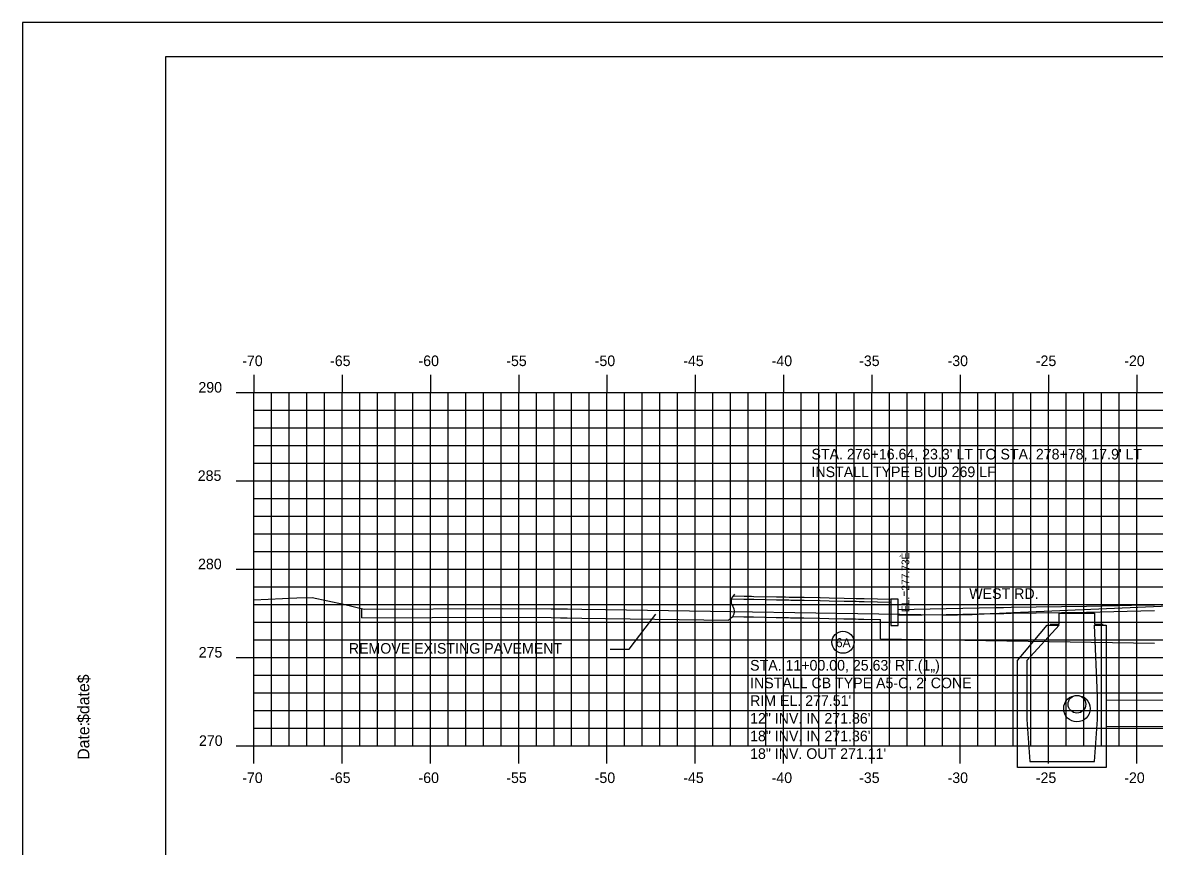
# Model space of a CAD drawing. Extents: x 853785 to 853955, y 366268 to 366378.
# Drawn here: x 853785.3 to 853849.4, y 366331.6 to 366378.2 of the extents above; entities that cross this region are included whole.
import ezdxf

# ---------------------------------------------------------------- set-up
doc = ezdxf.new("R2010")
doc.units = 0
for name, color, linetype in [('ANNOTATION', 7, 'Continuous'), ('BORDER', 7, 'Continuous'), ('D_Curb_Type1_Lt', 7, 'Continuous'), ('D_Drainage_CB_Shape5_Lt', 7, 'Continuous'), ('D_Drainage_Culvert', 7, 'Continuous'), ('D_Drainage_Text', 7, 'Continuous'), ('D_Roadway_Edge_Shoulder', 7, 'Continuous'), ('D_Roadway_Sidewalks_Paved', 7, 'Continuous'), ('D_Roadway_SubGrade', 7, 'Continuous'), ('D_Text_Standard', 7, 'Continuous'), ('H_V ANNOTATION', 7, 'Continuous'), ('MAJOR', 7, 'Continuous'), ('MINOR', 7, 'Continuous'), ('PDRAIN', 7, 'Continuous'), ('PLOT BOUNDARY', 7, 'Continuous'), ('S_Roadway_Centerline', 7, 'Continuous')]:
    doc.layers.add(name, color=color, linetype=linetype)

msp = doc.modelspace()

# ---------------------------------------------------------------- linework, layer by layer
at = {"layer": 'ANNOTATION'}
msp.add_lwpolyline([(853818.622, 366342.714), (853819.69, 366342.714), (853821.197, 366344.692)], dxfattribs=at)
at = {"layer": 'BORDER'}
for p, q in [((853953.435, 366376.236), (853793.435, 366376.236)), ((853793.435, 366376.236), (853793.435, 366271.236))]:
    msp.add_line(p, q, dxfattribs=at)
at = {"layer": 'D_Curb_Type1_Lt'}
msp.add_lwpolyline([(853834.514, 366345.548), (853834.514, 366344.048), (853834.931, 366344.048), (853834.931, 366345.548)], close=True, dxfattribs=at)
at = {"layer": 'D_Drainage_CB_Shape5_Lt'}
msp.add_lwpolyline([(853843.527, 366344.123), (853844.052, 366344.123), (853844.052, 366344.746), (853846.053, 366344.746), (853846.053, 366344.123), (853846.545, 366344.123)], dxfattribs=at)
msp.add_lwpolyline([(853846.709, 366344.081), (853846.709, 366336.018), (853841.689, 366336.018), (853841.689, 366342.081), (853843.363, 366344.081), (853844.052, 366344.081), (853842.214, 366342.081), (853842.214, 366340.079), (853842.214, 366338.734), (853842.378, 366336.346), (853846.053, 366336.346), (853846.217, 366338.734), (853846.217, 366340.079), (853846.053, 366344.081)], close=True, dxfattribs=at)
at = {"layer": 'D_Drainage_Culvert'}
for p, q in [((853846.709, 366339.851), (853883.967, 366339.636)), ((853846.709, 366338.351), (853883.958, 366338.136))]:
    msp.add_line(p, q, dxfattribs=at)
msp.add_circle((853845.052, 366339.346), 0.75, dxfattribs=at)
at = {"layer": 'D_Drainage_Text'}
msp.add_circle((853831.801, 366343.107), 0.625, dxfattribs=at)
at = {"layer": 'D_Roadway_Edge_Shoulder'}
for points in [[(853834.931, 366344.965), (853837.645, 366345.011), (853840.458, 366345.065), (853840.894, 366345.073), (853841.32, 366345.082), (853845.594, 366345.148), (853847.367, 366345.186), (853848.927, 366345.219), (853849.435, 366345.228)], [(853834.931, 366344.632), (853837.651, 366344.678), (853840.465, 366344.732), (853840.901, 366344.74), (853841.326, 366344.749), (853845.6, 366344.815), (853849.435, 366344.896)]]:
    msp.add_lwpolyline(points, dxfattribs=at)
at = {"layer": 'D_Roadway_Sidewalks_Paved'}
for points in [[(853825.482, 366345.559), (853826.195, 366345.546), (853826.246, 366345.545), (853826.275, 366345.544), (853826.621, 366345.538), (853826.74, 366345.536), (853826.758, 366345.536), (853828.04, 366345.511), (853828.543, 366345.502), (853828.742, 366345.498), (853828.852, 366345.496), (853829.597, 366345.481), (853830.507, 366345.463), (853831.016, 366345.453), (853831.868, 366345.436), (853832.538, 366345.423), (853832.708, 366345.419), (853832.998, 366345.413), (853834.511, 366345.382)], [(853825.566, 366345.724), (853826.198, 366345.713), (853826.249, 366345.712), (853826.278, 366345.711), (853826.624, 366345.705), (853826.744, 366345.702), (853826.761, 366345.702), (853828.043, 366345.677), (853828.546, 366345.668), (853828.745, 366345.664), (853828.855, 366345.662), (853829.6, 366345.648), (853830.51, 366345.63), (853831.02, 366345.619), (853831.871, 366345.603), (853832.541, 366345.589), (853832.712, 366345.586), (853833.001, 366345.58), (853834.514, 366345.549)]]:
    msp.add_lwpolyline(points, dxfattribs=at)
at = {"layer": 'D_Roadway_SubGrade'}
for p, q in [((853804.549, 366344.479), (853804.549, 366344.979)), ((853825.489, 366344.501), (853825.312, 366344.35)), ((853833.931, 366343.3), (853833.931, 366344.392)), ((853833.931, 366343.3), (853849.435, 366343.056))]:
    msp.add_line(p, q, dxfattribs=at)
for points in [[(853804.549, 366344.479), (853812.519, 366344.519), (853815.27, 366344.497), (853815.804, 366344.491), (853816.186, 366344.487), (853817.006, 366344.476), (853818.343, 366344.458), (853825.312, 366344.35)], [(853825.545, 366344.558), (853826.177, 366344.546), (853826.229, 366344.545), (853826.257, 366344.545), (853826.602, 366344.538), (853826.722, 366344.536), (853826.74, 366344.536), (853828.021, 366344.511), (853828.524, 366344.502), (853828.723, 366344.498), (853828.833, 366344.496), (853829.578, 366344.482), (853830.486, 366344.464), (853830.996, 366344.453), (853831.848, 366344.436), (853832.517, 366344.423), (853832.687, 366344.419), (853832.977, 366344.413), (853833.931, 366344.394)]]:
    msp.add_lwpolyline(points, dxfattribs=at)
for centre, radius, start, end in [((853825.95, 366345.425), 0.486, 125.81593, 215.81593), ((853825.207, 366344.854), 0.452, 308.64564, 39.40492)]:
    msp.add_arc(centre, radius, start, end, dxfattribs=at)
at = {"layer": 'MAJOR'}
for p, q in [((853798.435, 366358.238), (853798.435, 366357.236)), ((853803.435, 366358.238), (853803.435, 366357.236)), ((853808.435, 366358.238), (853808.435, 366357.236)), ((853813.435, 366358.238), (853813.435, 366357.236)), ((853818.435, 366358.238), (853818.435, 366357.236)), ((853823.435, 366358.238), (853823.435, 366357.236)), ((853828.435, 366358.238), (853828.435, 366357.236)), ((853833.435, 366358.238), (853833.435, 366357.236)), ((853838.435, 366358.238), (853838.435, 366357.236)), ((853843.435, 366358.238), (853843.435, 366357.236)), ((853848.435, 366358.238), (853848.435, 366357.236)), ((853797.433, 366357.236), (853798.435, 366357.236)), ((853798.435, 366357.236), (853938.435, 366357.236)), ((853798.435, 366337.236), (853798.435, 366357.236)), ((853798.435, 366337.236), (853798.435, 366357.236)), ((853798.435, 366357.236), (853938.435, 366357.236)), ((853803.435, 366337.236), (853803.435, 366357.236)), ((853808.435, 366337.236), (853808.435, 366357.236)), ((853813.435, 366337.236), (853813.435, 366357.236)), ((853818.435, 366337.236), (853818.435, 366357.236)), ((853823.435, 366337.236), (853823.435, 366357.236)), ((853828.435, 366337.236), (853828.435, 366357.236)), ((853833.435, 366337.236), (853833.435, 366357.236)), ((853838.435, 366337.236), (853838.435, 366357.236)), ((853843.435, 366337.236), (853843.435, 366357.236)), ((853848.435, 366337.236), (853848.435, 366357.236)), ((853797.433, 366352.236), (853798.435, 366352.236)), ((853798.435, 366352.236), (853938.435, 366352.236)), ((853797.433, 366347.236), (853798.435, 366347.236)), ((853798.435, 366347.236), (853938.435, 366347.236)), ((853797.433, 366342.236), (853798.435, 366342.236)), ((853798.435, 366342.236), (853938.435, 366342.236)), ((853797.433, 366337.236), (853798.435, 366337.236)), ((853798.435, 366337.236), (853938.435, 366337.236)), ((853798.435, 366337.236), (853938.435, 366337.236)), ((853798.435, 366336.234), (853798.435, 366337.236)), ((853803.435, 366336.234), (853803.435, 366337.236)), ((853808.435, 366336.234), (853808.435, 366337.236)), ((853813.435, 366336.234), (853813.435, 366337.236)), ((853818.435, 366336.234), (853818.435, 366337.236)), ((853823.435, 366336.234), (853823.435, 366337.236)), ((853828.435, 366336.234), (853828.435, 366337.236)), ((853833.435, 366336.234), (853833.435, 366337.236)), ((853838.435, 366336.234), (853838.435, 366337.236)), ((853843.435, 366336.234), (853843.435, 366337.236)), ((853848.435, 366336.234), (853848.435, 366337.236))]:
    msp.add_line(p, q, dxfattribs=at)
at = {"layer": 'MINOR'}
for p, q in [((853799.435, 366337.236), (853799.435, 366357.236)), ((853800.435, 366337.236), (853800.435, 366357.236)), ((853801.435, 366337.236), (853801.435, 366357.236)), ((853802.435, 366337.236), (853802.435, 366357.236)), ((853804.435, 366337.236), (853804.435, 366357.236)), ((853805.435, 366337.236), (853805.435, 366357.236)), ((853806.435, 366337.236), (853806.435, 366357.236)), ((853807.435, 366337.236), (853807.435, 366357.236)), ((853809.435, 366337.236), (853809.435, 366357.236)), ((853810.435, 366337.236), (853810.435, 366357.236)), ((853811.435, 366337.236), (853811.435, 366357.236)), ((853812.435, 366337.236), (853812.435, 366357.236)), ((853814.435, 366337.236), (853814.435, 366357.236)), ((853815.435, 366337.236), (853815.435, 366357.236)), ((853816.435, 366337.236), (853816.435, 366357.236)), ((853817.435, 366337.236), (853817.435, 366357.236)), ((853819.435, 366337.236), (853819.435, 366357.236)), ((853820.435, 366337.236), (853820.435, 366357.236)), ((853821.435, 366337.236), (853821.435, 366357.236)), ((853822.435, 366337.236), (853822.435, 366357.236)), ((853824.435, 366337.236), (853824.435, 366357.236)), ((853825.435, 366337.236), (853825.435, 366357.236)), ((853826.435, 366337.236), (853826.435, 366357.236)), ((853827.435, 366337.236), (853827.435, 366357.236)), ((853829.435, 366337.236), (853829.435, 366357.236)), ((853830.435, 366337.236), (853830.435, 366357.236)), ((853831.435, 366337.236), (853831.435, 366357.236)), ((853832.435, 366337.236), (853832.435, 366357.236)), ((853834.435, 366337.236), (853834.435, 366357.236)), ((853835.435, 366337.236), (853835.435, 366357.236)), ((853836.435, 366337.236), (853836.435, 366357.236)), ((853837.435, 366337.236), (853837.435, 366357.236)), ((853839.435, 366337.236), (853839.435, 366357.236)), ((853840.435, 366337.236), (853840.435, 366357.236)), ((853841.435, 366337.236), (853841.435, 366357.236)), ((853842.435, 366337.236), (853842.435, 366357.236)), ((853844.435, 366337.236), (853844.435, 366357.236)), ((853845.435, 366337.236), (853845.435, 366357.236)), ((853846.435, 366337.236), (853846.435, 366357.236)), ((853847.435, 366337.236), (853847.435, 366357.236)), ((853798.435, 366356.236), (853938.435, 366356.236)), ((853798.435, 366356.236), (853799.437, 366356.236)), ((853798.435, 366355.236), (853938.435, 366355.236)), ((853798.435, 366355.236), (853799.437, 366355.236)), ((853798.435, 366354.236), (853938.435, 366354.236)), ((853798.435, 366354.236), (853799.437, 366354.236)), ((853798.435, 366353.236), (853938.435, 366353.236)), ((853798.435, 366353.236), (853799.437, 366353.236)), ((853798.435, 366351.236), (853938.435, 366351.236)), ((853798.435, 366351.236), (853799.437, 366351.236)), ((853798.435, 366350.236), (853938.435, 366350.236)), ((853798.435, 366350.236), (853799.437, 366350.236)), ((853798.435, 366349.236), (853938.435, 366349.236)), ((853798.435, 366349.236), (853799.437, 366349.236)), ((853798.435, 366348.236), (853938.435, 366348.236)), ((853798.435, 366348.236), (853799.437, 366348.236)), ((853798.435, 366346.236), (853938.435, 366346.236)), ((853798.435, 366346.236), (853799.437, 366346.236)), ((853798.435, 366345.236), (853938.435, 366345.236)), ((853798.435, 366345.236), (853799.437, 366345.236)), ((853798.435, 366344.236), (853938.435, 366344.236)), ((853798.435, 366344.236), (853799.437, 366344.236)), ((853798.435, 366343.236), (853938.435, 366343.236)), ((853798.435, 366343.236), (853799.437, 366343.236)), ((853798.435, 366341.236), (853938.435, 366341.236)), ((853798.435, 366341.236), (853799.437, 366341.236)), ((853798.435, 366340.236), (853938.435, 366340.236)), ((853798.435, 366340.236), (853799.437, 366340.236)), ((853798.435, 366339.236), (853938.435, 366339.236)), ((853798.435, 366339.236), (853799.437, 366339.236)), ((853798.435, 366338.236), (853938.435, 366338.236)), ((853798.435, 366338.236), (853799.437, 366338.236))]:
    msp.add_line(p, q, dxfattribs=at)
at = {"layer": 'PDRAIN'}
msp.add_circle((853845.052, 366339.596), 0.5, dxfattribs=at)
at = {"layer": 'PLOT BOUNDARY'}
msp.add_lwpolyline([(853785.342, 366268.177), (853955.342, 366268.177), (853955.342, 366378.177), (853785.342, 366378.177)], close=True, dxfattribs=at)
at = {"layer": 'S_Roadway_Centerline'}
msp.add_lwpolyline([(853798.435, 366345.505), (853800.867, 366345.626), (853801.744, 366345.632), (853803.506, 366345.26), (853804.681, 366344.98), (853812.519, 366345.019), (853815.274, 366344.996), (853815.81, 366344.991), (853816.193, 366344.987), (853817.013, 366344.975), (853818.35, 366344.958), (853837.4, 366344.662), (853837.904, 366344.661), (853838.283, 366344.664), (853839.115, 366344.681), (853840.138, 366344.725), (853840.656, 366344.753), (853841.417, 366344.797), (853851.596, 366345.229)], dxfattribs=at)

# ---------------------------------------------------------------- texts
at = {"layer": 'BORDER'}
for s, p in [('$date$', (853789.12, 366338.542)), ('Date:', (853789.12, 366336.453))]:
    msp.add_text(s, height=0.6696, rotation=90, dxfattribs=at).set_placement(p)
at = {"layer": 'D_Drainage_Text'}
for s, p in [("STA. 276+16.64, 23.3' LT TO STA. 278+78, 17.9' LT", (853830.017, 366353.452)), ('INSTALL TYPE B UD 269 LF', (853830.017, 366352.452)), ("STA. 11+00.00, 25.63' RT.(1„)", (853826.54, 366341.501)), ("INSTALL CB TYPE A5-C, 2' CONE", (853826.54, 366340.501)), ("RIM EL. 277.51'", (853826.54, 366339.501)), ('12" INV. IN 271.86\'', (853826.54, 366338.501)), ('18" INV. IN 271.36\'', (853826.54, 366337.501)), ('18" INV. OUT 271.11\'', (853826.54, 366336.501))]:
    msp.add_text(s, height=0.6, dxfattribs=at).set_placement(p)
at = {"layer": 'D_Text_Standard'}
msp.add_text(' EL.=277.73È', height=0.4335, rotation=90, dxfattribs=at).set_placement((853835.552, 366344.654))
for s, p in [('WEST RD.', (853838.953, 366345.558)), ('REMOVE EXISTING PAVEMENT', (853803.814, 366342.46))]:
    msp.add_text(s, height=0.6, dxfattribs=at).set_placement(p)
at = {"layer": 'H_V ANNOTATION'}
for s, height, p in [('-70', 0.6, (853797.777, 366358.736)), ('-65', 0.6, (853802.753, 366358.736)), ('-60', 0.6, (853807.761, 366358.736)), ('-55', 0.6, (853812.731, 366358.736)), ('-50', 0.6, (853817.739, 366358.736)), ('-45', 0.6, (853822.753, 366358.736)), ('-40', 0.6, (853827.761, 366358.736)), ('-35', 0.6, (853832.715, 366358.736)), ('-30', 0.6, (853837.723, 366358.736)), ('-25', 0.6, (853842.721, 366358.736)), ('-20', 0.6, (853847.729, 366358.736)), ('290', 0.6, (853795.297, 366357.236)), ('285', 0.6, (853795.26, 366352.236)), ('280', 0.6, (853795.276, 366347.236)), ('6A', 0.51, (853831.397, 366342.824)), ('275', 0.6, (853795.313, 366342.236)), ('270', 0.6, (853795.329, 366337.236)), ('-70', 0.6, (853797.777, 366335.136)), ('-65', 0.6, (853802.753, 366335.136)), ('-60', 0.6, (853807.761, 366335.136)), ('-55', 0.6, (853812.731, 366335.136)), ('-50', 0.6, (853817.739, 366335.136)), ('-45', 0.6, (853822.753, 366335.136)), ('-40', 0.6, (853827.761, 366335.136)), ('-35', 0.6, (853832.715, 366335.136)), ('-30', 0.6, (853837.723, 366335.136)), ('-25', 0.6, (853842.721, 366335.136)), ('-20', 0.6, (853847.729, 366335.136))]:
    msp.add_text(s, height=height, dxfattribs=at).set_placement(p)

doc.saveas('drawing.dxf')
